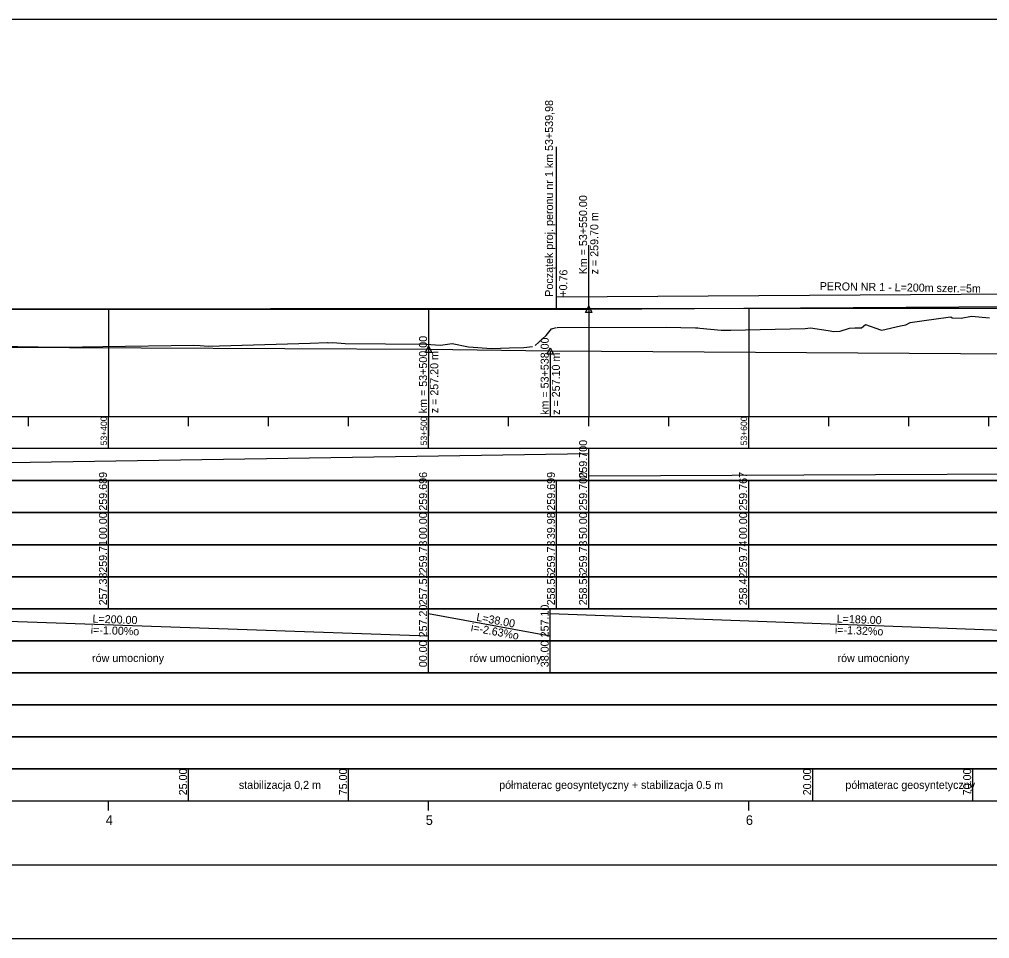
# Model space of a CAD drawing. Extents: x 6445630 to 6518227, y 5499240 to 5511716.
# Drawn here: x 6452603.3 to 6452906.5, y 5508966.7 to 5509253.7 of the extents above; entities that cross this region are included whole.
import ezdxf

# ---------------------------------------------------------------- set-up
doc = ezdxf.new("R2010")
doc.units = 0
for name, color, linetype in [('Default', 7, 'Continuous'), ('TOR_PROF-obiekty+opisy', 7, 'Continuous'), ('TOR_PROF-opisy pomocnicze', 7, 'Continuous'), ('TOR_PROF-rowy otwarte', 7, 'Continuous'), ('TOR_PROF-tabelka-geometria T1', 7, 'Continuous'), ('TOR_PROF-tabelka-kilometracja', 7, 'Continuous'), ('TOR_PROF-tabelka-odleglosci T1', 7, 'Continuous'), ('TOR_PROF-tabelka-pochylenia proj T1', 7, 'Continuous'), ('TOR_PROF-tabelka-rodzaj rowu T1', 7, 'Continuous'), ('TOR_PROF-tabelka-rowyT1', 7, 'Continuous'), ('TOR_PROF-tabelka-rurociagi T1', 7, 'Continuous'), ('TOR_PROF-tabelka-rzedne istn T1', 7, 'Continuous'), ('TOR_PROF-tabelka-rzedne proj T1', 7, 'Continuous'), ('TOR_PROF-tabelka-teren istniejacy T1', 7, 'Continuous'), ('TOR_PROF-tabelka-warstwa ochronna T1', 7, 'Continuous'), ('TOR_PROF-tor istniejacy T1', 7, 'Continuous'), ('TOR_PROF-tor projektowany', 7, 'Continuous'), ('TOR_PROF-uklad odniesienia', 7, 'Continuous'), ('TOR_PROF-warstwa ochronna', 7, 'Continuous'), ('TOR_RAMKI-dodatkowe3', 7, 'Continuous'), ('TOR_RAMKI-MASKA WYCIECIA', 7, 'Continuous')]:
    doc.layers.add(name, color=color, linetype=linetype)

msp = doc.modelspace()

# ---------------------------------------------------------------- linework, layer by layer
at = {"layer": 'TOR_PROF-obiekty+opisy'}
for p, q in [((6452771.19, 5509167.03), (6452771.19, 5509214.01)), ((6452971.19, 5509168.3), (6452771.19, 5509167.03)), ((6452771.19, 5509163.23), (6452771.19, 5509167.03))]:
    msp.add_line(p, q, dxfattribs=at)
at = {"layer": 'TOR_PROF-opisy pomocnicze'}
for p, q in [((6452781.21, 5509163.24), (6452781.21, 5509183.24)), ((6452781.21, 5509163.24), (6452781.21, 5509183.24)), ((6452731.21, 5509150.74), (6452731.21, 5509123.74)), ((6452769.21, 5509150.24), (6452769.21, 5509129.74))]:
    msp.add_line(p, q, dxfattribs=at)
for points in [[(6452781.21, 5509164.24), (6452782.21, 5509162.24), (6452780.21, 5509162.24)], [(6452781.21, 5509164.24), (6452782.21, 5509162.24), (6452780.21, 5509162.24)], [(6452731.21, 5509151.74), (6452732.21, 5509149.74), (6452730.21, 5509149.74)], [(6452769.21, 5509151.24), (6452770.21, 5509149.24), (6452768.21, 5509149.24)]]:
    msp.add_lwpolyline(points, close=True, dxfattribs=at)
at = {"layer": 'TOR_PROF-rowy otwarte'}
for p, q in [((6452531.21, 5509151.74), (6452731.21, 5509150.74)), ((6452731.21, 5509150.74), (6452769.21, 5509150.24)), ((6452769.21, 5509150.24), (6452958.21, 5509148.99))]:
    msp.add_line(p, q, dxfattribs=at)
for points in [[(6452731.21, 5509150.74), (6452731.21, 5509134.74), (6452731.21, 5509129.74), (6452731.21, 5509129.74)], [(6452769.21, 5509150.24), (6452769.21, 5509134.74), (6452769.21, 5509129.74), (6452769.21, 5509129.74)]]:
    msp.add_lwpolyline(points, dxfattribs=at)
at = {"layer": 'TOR_PROF-tabelka-geometria T1'}
for points in [[(6452331.21, 5508989.74), (6462728.4, 5508989.74)], [(6452331.21, 5508989.74), (6462731.21, 5508989.74)]]:
    msp.add_lwpolyline(points, dxfattribs=at)
at = {"layer": 'TOR_PROF-tabelka-kilometracja'}
for points in [[(6452631.21, 5509006.74), (6452631.21, 5509009.74)], [(6452731.21, 5509006.74), (6452731.21, 5509009.74)], [(6452831.21, 5509006.74), (6452831.21, 5509009.74)]]:
    msp.add_lwpolyline(points, dxfattribs=at)
at = {"layer": 'TOR_PROF-tabelka-odleglosci T1'}
msp.add_lwpolyline([(6452331.21, 5509089.74), (6462731.21, 5509089.74), (6462731.21, 5509099.74), (6452331.21, 5509099.74)], close=True, dxfattribs=at)
for points in [[(6452631.21, 5509089.74), (6452631.21, 5509099.74)], [(6452731.21, 5509089.74), (6452731.21, 5509099.74)], [(6452771.19, 5509089.74), (6452771.19, 5509099.74)], [(6452781.21, 5509089.74), (6452781.21, 5509099.74)], [(6452831.21, 5509089.74), (6452831.21, 5509099.74)]]:
    msp.add_lwpolyline(points, dxfattribs=at)
at = {"layer": 'TOR_PROF-tabelka-pochylenia proj T1'}
msp.add_lwpolyline([(6452331.21, 5509109.74), (6462731.21, 5509109.74), (6462731.21, 5509119.74), (6452331.21, 5509119.74)], close=True, dxfattribs=at)
for points in [[(6452781.21, 5509109.74), (6452781.21, 5509119.74)], [(6452331.21, 5509111.24), (6452781.21, 5509118.24)], [(6452781.21, 5509111.24), (6454281.21, 5509118.24)]]:
    msp.add_lwpolyline(points, dxfattribs=at)
at = {"layer": 'TOR_PROF-tabelka-rodzaj rowu T1'}
for points in [[(6452331.21, 5509049.74), (6462731.21, 5509049.74), (6462731.21, 5509059.74), (6452331.21, 5509059.74)], [(6452331.21, 5509029.74), (6462731.21, 5509029.74), (6462731.21, 5509039.74), (6452331.21, 5509039.74)]]:
    msp.add_lwpolyline(points, close=True, dxfattribs=at)
for points in [[(6452731.21, 5509049.74), (6452731.21, 5509059.74)], [(6452769.21, 5509049.74), (6452769.21, 5509059.74)]]:
    msp.add_lwpolyline(points, dxfattribs=at)
at = {"layer": 'TOR_PROF-tabelka-rowyT1'}
msp.add_lwpolyline([(6452331.21, 5509059.74), (6462731.21, 5509059.74), (6462731.21, 5509069.74), (6452331.21, 5509069.74)], close=True, dxfattribs=at)
for points in [[(6452531.21, 5509068.24), (6452731.21, 5509061.24)], [(6452731.21, 5509059.74), (6452731.21, 5509069.74)], [(6452731.21, 5509068.24), (6452769.21, 5509061.24)], [(6452769.21, 5509059.74), (6452769.21, 5509069.74)], [(6452769.21, 5509068.24), (6452958.21, 5509061.24)]]:
    msp.add_lwpolyline(points, dxfattribs=at)
at = {"layer": 'TOR_PROF-tabelka-rurociagi T1'}
msp.add_lwpolyline([(6452331.21, 5509039.74), (6462731.21, 5509039.74), (6462731.21, 5509049.74), (6452331.21, 5509049.74)], close=True, dxfattribs=at)
at = {"layer": 'TOR_PROF-tabelka-rzedne istn T1'}
msp.add_lwpolyline([(6452331.21, 5509079.74), (6462731.21, 5509079.74), (6462731.21, 5509089.74), (6452331.21, 5509089.74)], close=True, dxfattribs=at)
for points in [[(6452631.21, 5509079.74), (6452631.21, 5509089.74)], [(6452731.21, 5509079.74), (6452731.21, 5509089.74)], [(6452771.19, 5509079.74), (6452771.19, 5509089.74)], [(6452781.21, 5509079.74), (6452781.21, 5509089.74)], [(6452831.21, 5509079.74), (6452831.21, 5509089.74)], [(6452631.21, 5509069.74), (6452631.21, 5509079.74)], [(6452631.21, 5509069.74), (6452631.21, 5509079.74)], [(6452631.21, 5509069.74), (6452631.21, 5509079.74)], [(6452631.21, 5509069.74), (6452631.21, 5509079.74)], [(6452631.21, 5509069.74), (6452631.21, 5509079.74)], [(6452731.21, 5509069.74), (6452731.21, 5509079.74)], [(6452731.21, 5509069.74), (6452731.21, 5509079.74)], [(6452731.21, 5509069.74), (6452731.21, 5509079.74)], [(6452731.21, 5509069.74), (6452731.21, 5509079.74)], [(6452731.21, 5509069.74), (6452731.21, 5509079.74)], [(6452771.19, 5509069.74), (6452771.19, 5509079.74)], [(6452781.21, 5509069.74), (6452781.21, 5509079.74)], [(6452831.21, 5509069.74), (6452831.21, 5509079.74)], [(6452831.21, 5509069.74), (6452831.21, 5509079.74)], [(6452831.21, 5509069.74), (6452831.21, 5509079.74)], [(6452831.21, 5509069.74), (6452831.21, 5509079.74)], [(6452831.21, 5509069.74), (6452831.21, 5509079.74)]]:
    msp.add_lwpolyline(points, dxfattribs=at)
at = {"layer": 'TOR_PROF-tabelka-rzedne proj T1'}
msp.add_lwpolyline([(6452331.21, 5509099.74), (6462731.21, 5509099.74), (6462731.21, 5509109.74), (6452331.21, 5509109.74)], close=True, dxfattribs=at)
for points in [[(6452631.21, 5509099.74), (6452631.21, 5509109.74)], [(6452731.21, 5509099.74), (6452731.21, 5509109.74)], [(6452771.19, 5509099.74), (6452771.19, 5509109.74)], [(6452781.21, 5509099.74), (6452781.21, 5509109.74)], [(6452831.21, 5509099.74), (6452831.21, 5509109.74)]]:
    msp.add_lwpolyline(points, dxfattribs=at)
at = {"layer": 'TOR_PROF-tabelka-teren istniejacy T1'}
msp.add_lwpolyline([(6452331.21, 5509069.74), (6462731.21, 5509069.74), (6462731.21, 5509079.74), (6452331.21, 5509079.74)], close=True, dxfattribs=at)
msp.add_lwpolyline([(6452331.21, 5509069.74), (6462731.21, 5509069.74), (6462731.21, 5509079.74), (6452331.21, 5509079.74)], close=True, dxfattribs=at)
msp.add_lwpolyline([(6452331.21, 5509069.74), (6462731.21, 5509069.74), (6462731.21, 5509079.74), (6452331.21, 5509079.74)], close=True, dxfattribs=at)
msp.add_lwpolyline([(6452331.21, 5509069.74), (6462731.21, 5509069.74), (6462731.21, 5509079.74), (6452331.21, 5509079.74)], close=True, dxfattribs=at)
msp.add_lwpolyline([(6452331.21, 5509069.74), (6462731.21, 5509069.74), (6462731.21, 5509079.74), (6452331.21, 5509079.74)], close=True, dxfattribs=at)
at = {"layer": 'TOR_PROF-tabelka-warstwa ochronna T1'}
msp.add_lwpolyline([(6452331.21, 5509019.74), (6462731.21, 5509019.74), (6462731.21, 5509029.74), (6452331.21, 5509029.74)], close=True, dxfattribs=at)
at = {"layer": 'TOR_PROF-tor istniejacy T1'}
msp.add_lwpolyline([(6452931.09, 5509163.44), (6452879.94, 5509163.44), (6452829.7, 5509163.44), (6452781, 5509163.39), (6452734.97, 5509163.39), (6452681.81, 5509163.34), (6452629.5, 5509163.29), (6452580.86, 5509163.34), (6452530.02, 5509163.29), (6452479.81, 5509163.34), (6452430.6, 5509163.29), (6452380.83, 5509163.19), (6452331.21, 5509163.19)], dxfattribs=at)
at = {"layer": 'TOR_PROF-tor projektowany'}
for p, q in [((6452781.21, 5509163.24), (6454281.21, 5509173.24)), ((6452781.21, 5509163.24), (6454281.21, 5509173.24)), ((6452331.21, 5509163.07), (6452781.21, 5509163.24)), ((6452331.21, 5509163.07), (6452781.21, 5509163.24))]:
    msp.add_line(p, q, dxfattribs=at)
for points in [[(6452631.21, 5509163.18), (6452631.21, 5509134.74), (6452631.21, 5509129.74), (6452631.21, 5509129.74)], [(6452631.21, 5509163.18), (6452631.21, 5509134.74), (6452631.21, 5509129.74), (6452631.21, 5509129.74)], [(6452731.21, 5509163.22), (6452731.21, 5509134.74), (6452731.21, 5509129.74), (6452731.21, 5509129.74)], [(6452731.21, 5509163.22), (6452731.21, 5509134.74), (6452731.21, 5509129.74), (6452731.21, 5509129.74)], [(6452781.21, 5509163.24), (6452781.21, 5509134.74), (6452781.21, 5509129.74), (6452781.21, 5509129.74)], [(6452781.21, 5509163.24), (6452781.21, 5509134.74), (6452781.21, 5509129.74), (6452781.21, 5509129.74)], [(6452781.21, 5509163.24), (6452781.21, 5509134.74), (6452781.21, 5509129.74), (6452781.21, 5509129.74)], [(6452781.21, 5509163.24), (6452781.21, 5509134.74), (6452781.21, 5509129.74), (6452781.21, 5509129.74)], [(6452781.21, 5509163.24), (6452781.21, 5509134.74), (6452781.21, 5509129.74), (6452781.21, 5509129.74)], [(6452831.21, 5509163.57), (6452831.21, 5509134.74), (6452831.21, 5509129.74), (6452831.21, 5509129.74)], [(6452831.21, 5509163.57), (6452831.21, 5509134.74), (6452831.21, 5509129.74), (6452831.21, 5509129.74)]]:
    msp.add_lwpolyline(points, dxfattribs=at)
at = {"layer": 'TOR_PROF-uklad odniesienia'}
for p, q in [((6452331.21, 5509129.74), (6462731.21, 5509129.74)), ((6452606.21, 5509126.74), (6452606.21, 5509129.74)), ((6452631.21, 5509119.74), (6452631.21, 5509129.74)), ((6452656.21, 5509126.74), (6452656.21, 5509129.74)), ((6452681.21, 5509126.74), (6452681.21, 5509129.74)), ((6452706.21, 5509126.74), (6452706.21, 5509129.74)), ((6452731.21, 5509119.74), (6452731.21, 5509129.74)), ((6452756.21, 5509126.74), (6452756.21, 5509129.74)), ((6452781.21, 5509126.74), (6452781.21, 5509129.74)), ((6452806.21, 5509126.74), (6452806.21, 5509129.74)), ((6452831.21, 5509119.74), (6452831.21, 5509129.74)), ((6452856.21, 5509126.74), (6452856.21, 5509129.74)), ((6452881.21, 5509126.74), (6452881.21, 5509129.74)), ((6452906.21, 5509126.74), (6452906.21, 5509129.74))]:
    msp.add_line(p, q, dxfattribs=at)
at = {"layer": 'TOR_PROF-warstwa ochronna'}
msp.add_lwpolyline([(6452331.21, 5509009.74), (6462731.21, 5509009.74), (6462731.21, 5509019.74), (6452331.21, 5509019.74)], close=True, dxfattribs=at)
for points in [[(6452656.21, 5509009.74), (6452656.21, 5509019.74)], [(6452706.21, 5509009.74), (6452706.21, 5509019.74)], [(6452851.21, 5509009.74), (6452851.21, 5509019.74)], [(6452901.21, 5509009.74), (6452901.21, 5509019.74)]]:
    msp.add_lwpolyline(points, dxfattribs=at)
at = {"layer": 'TOR_RAMKI-dodatkowe3'}
for p, q in [((6452866.41, 5509157.4), (6452867.66, 5509158.54)), ((6452867.66, 5509158.54), (6452872.38, 5509156.87)), ((6452880.34, 5509158.36), (6452881.67, 5509159.15)), ((6452881.67, 5509159.15), (6452886.05, 5509159.69)), ((6452886.05, 5509159.69), (6452893.51, 5509160.81)), ((6452893.51, 5509160.81), (6452894.35, 5509160.92)), ((6452894.35, 5509160.92), (6452894.74, 5509160.53)), ((6452894.74, 5509160.53), (6452897.58, 5509160.46)), ((6452897.58, 5509160.46), (6452900.84, 5509161.04)), ((6452900.84, 5509161.04), (6452906.46, 5509160.62)), ((6452767.93, 5509155.01), (6452769.62, 5509157.11)), ((6452769.62, 5509157.11), (6452771.11, 5509157.53)), ((6452771.32, 5509157.51), (6452805.45, 5509157.62)), ((6452805.45, 5509157.62), (6452814.62, 5509157.45)), ((6452814.62, 5509157.45), (6452815.27, 5509157.44)), ((6452815.34, 5509157.44), (6452815.91, 5509157.37)), ((6452815.91, 5509157.37), (6452822.62, 5509156.7)), ((6452822.62, 5509156.7), (6452825.61, 5509156.73)), ((6452825.61, 5509156.73), (6452834.76, 5509156.93)), ((6452834.76, 5509156.93), (6452848.87, 5509157.24)), ((6452848.87, 5509157.24), (6452850.55, 5509157.44)), ((6452850.55, 5509157.44), (6452856, 5509156.59)), ((6452856, 5509156.59), (6452857.79, 5509156.35)), ((6452857.79, 5509156.35), (6452859.76, 5509156.38)), ((6452859.76, 5509156.38), (6452862.68, 5509157.31)), ((6452862.68, 5509157.31), (6452864.34, 5509157.43)), ((6452864.34, 5509157.43), (6452866.41, 5509157.4)), ((6452872.38, 5509156.87), (6452872.79, 5509156.75)), ((6452872.79, 5509156.75), (6452878.64, 5509158.03)), ((6452878.64, 5509158.03), (6452880.34, 5509158.36)), ((6452662.33, 5509151.75), (6452694.15, 5509152.64)), ((6452694.15, 5509152.64), (6452699.5, 5509152.84)), ((6452699.5, 5509152.84), (6452699.82, 5509152.8)), ((6452699.82, 5509152.8), (6452701.31, 5509152.88)), ((6452701.31, 5509152.88), (6452705.13, 5509152.59)), ((6452705.13, 5509152.59), (6452730.35, 5509152.37)), ((6452730.35, 5509152.37), (6452734.89, 5509152.08)), ((6452734.89, 5509152.08), (6452738.6, 5509152.56)), ((6452738.6, 5509152.56), (6452743.67, 5509151.49)), ((6452764.49, 5509151.9), (6452767.93, 5509155.01)), ((6452561.28, 5509152.33), (6452615.52, 5509151.42)), ((6452615.52, 5509151.42), (6452621.15, 5509151.4)), ((6452621.15, 5509151.4), (6452623.11, 5509151.49)), ((6452623.11, 5509151.49), (6452629.4, 5509151.59)), ((6452629.4, 5509151.59), (6452657.87, 5509152.02)), ((6452657.87, 5509152.02), (6452659.81, 5509151.95)), ((6452659.81, 5509151.95), (6452662.33, 5509151.75)), ((6452743.67, 5509151.49), (6452750.84, 5509151.04)), ((6452750.84, 5509151.04), (6452756.52, 5509151.24)), ((6452756.52, 5509151.24), (6452760.97, 5509151.34)), ((6452760.97, 5509151.34), (6452763.69, 5509151.66))]:
    msp.add_line(p, q, dxfattribs=at)
at = {"layer": 'TOR_RAMKI-MASKA WYCIECIA'}
msp.add_lwpolyline([(6452263.34, 5508966.75), (6454333.34, 5508966.75), (6454333.34, 5509253.75), (6452263.34, 5509253.75)], close=True, dxfattribs=at)

# ---------------------------------------------------------------- texts
at = {"layer": 'Default'}
for p in [(6452629.5, 5509163.29), (6452681.81, 5509163.34), (6452734.97, 5509163.39), (6452781, 5509163.39), (6452829.7, 5509163.44), (6452879.94, 5509163.44)]:
    msp.add_text('+', height=0.001, dxfattribs=at).set_placement(p)
at = {"layer": 'TOR_PROF-obiekty+opisy'}
for s, rotation, p in [('Początek proj. peronu nr 1 km 53+539,98', 90, (6452770.08, 5509167.16)), ('+0.76', 89.0973, (6452774.44, 5509167.15)), ('PERON NR 1 - L=200m szer.=5m ', 359.0973, (6452853.38, 5509169.24))]:
    msp.add_text(s, height=2.5, rotation=rotation, dxfattribs=at).set_placement(p)
at = {"layer": 'TOR_PROF-opisy pomocnicze'}
for s, p in [('Km = 53+550.00', (6452780.71, 5509174.14)), ('Km = 53+550.00', (6452780.71, 5509174.14)), ('z = 259.70 m', (6452784.21, 5509174.14)), ('z = 259.70 m', (6452784.21, 5509174.14)), ('km = 53+500.00', (6452730.71, 5509130.78)), ('km = 53+538.00', (6452768.71, 5509130.28)), ('z = 257.20 m', (6452734.21, 5509130.78)), ('z = 257.10 m', (6452772.21, 5509130.28))]:
    msp.add_text(s, height=2.5, rotation=90, dxfattribs=at).set_placement(p)
at = {"layer": 'TOR_PROF-tabelka-kilometracja'}
for s, p in [('4', (6452630.32, 5509002.24)), ('5', (6452730.31, 5509002.24)), ('6', (6452830.32, 5509002.24))]:
    msp.add_text(s, height=3, dxfattribs=at).set_placement(p)
at = {"layer": 'TOR_PROF-tabelka-odleglosci T1'}
for s, p in [('00.00', (6452630.71, 5509091.48)), ('00.00', (6452730.71, 5509091.48)), ('39.98', (6452770.69, 5509091.47)), ('50.00', (6452780.71, 5509091.48)), ('00.00', (6452830.71, 5509091.48))]:
    msp.add_text(s, height=2.5, rotation=90, dxfattribs=at).set_placement(p)
at = {"layer": 'TOR_PROF-tabelka-pochylenia proj T1'}
msp.add_text('259.700', height=2.5, rotation=90, dxfattribs=at).set_placement((6452780.71, 5509110.37))
at = {"layer": 'TOR_PROF-tabelka-rodzaj rowu T1'}
for s, p in [('00.00', (6452730.71, 5509051.48)), ('38.00', (6452768.71, 5509051.48))]:
    msp.add_text(s, height=2.5, rotation=90, dxfattribs=at).set_placement(p)
at = {"layer": 'TOR_PROF-tabelka-rowyT1'}
for s, rotation, p in [('257.20', 90, (6452730.71, 5509060.8)), ('257.10', 90, (6452768.71, 5509060.8)), ('L=200.00', 357.9955, (6452626.16, 5509065.41)), ('L=38.00', 349.5625, (6452745.98, 5509066.02)), ('L=189.00', 357.8789, (6452858.66, 5509065.42)), ('i=-1.00%o', 357.9955, (6452625.61, 5509061.93)), ('i=-2.63%o', 349.5625, (6452744.26, 5509062.78)), ('i=-1.32%o', 357.8789, (6452858.1, 5509061.94)), ('rów umocniony', 0.087, (6452626.06, 5509053.08)), ('rów umocniony', 0.087, (6452743.99, 5509053.08)), ('rów umocniony', 0.087, (6452858.96, 5509053.08))]:
    msp.add_text(s, height=2.5, rotation=rotation, dxfattribs=at).set_placement(p)
at = {"layer": 'TOR_PROF-tabelka-rzedne istn T1'}
for s, p in [('259.71', (6452630.71, 5509080.97)), ('259.73', (6452730.71, 5509080.8)), ('259.73', (6452770.69, 5509080.8)), ('259.73', (6452780.71, 5509080.8)), ('259.74', (6452830.71, 5509080.8)), ('257.38', (6452630.71, 5509070.8)), ('257.52', (6452730.71, 5509070.81)), ('258.56', (6452770.69, 5509070.8)), ('258.56', (6452780.71, 5509070.8)), ('258.42', (6452830.71, 5509070.81))]:
    msp.add_text(s, height=2.5, rotation=90, dxfattribs=at).set_placement(p)
at = {"layer": 'TOR_PROF-tabelka-rzedne proj T1'}
for s, p in [('259.689', (6452630.71, 5509100.37)), ('259.696', (6452730.71, 5509100.37)), ('259.699', (6452770.69, 5509100.37)), ('259.700', (6452780.71, 5509100.37)), ('259.767', (6452830.71, 5509100.37))]:
    msp.add_text(s, height=2.5, rotation=90, dxfattribs=at).set_placement(p)
at = {"layer": 'TOR_PROF-uklad odniesienia'}
for s, p in [('53+400', (6452630.71, 5509120.76)), ('53+500', (6452730.71, 5509120.76)), ('53+600', (6452830.71, 5509120.76))]:
    msp.add_text(s, height=2, rotation=90, dxfattribs=at).set_placement(p)
at = {"layer": 'TOR_PROF-warstwa ochronna'}
for s, p in [('25.00', (6452655.71, 5509011.48)), ('75.00', (6452705.71, 5509011.48)), ('20.00', (6452850.71, 5509011.48)), ('70.00', (6452900.71, 5509011.48))]:
    msp.add_text(s, height=2.5, rotation=90, dxfattribs=at).set_placement(p)
for s, p in [('stabilizacja 0,2 m', (6452671.92, 5509013.49)), ('półmaterac geosyntetyczny + stabilizacja 0.5 m', (6452753.25, 5509013.49)), ('półmaterac geosyntetyczny', (6452861.42, 5509013.49))]:
    msp.add_text(s, height=2.5, dxfattribs=at).set_placement(p)

doc.saveas('drawing.dxf')
